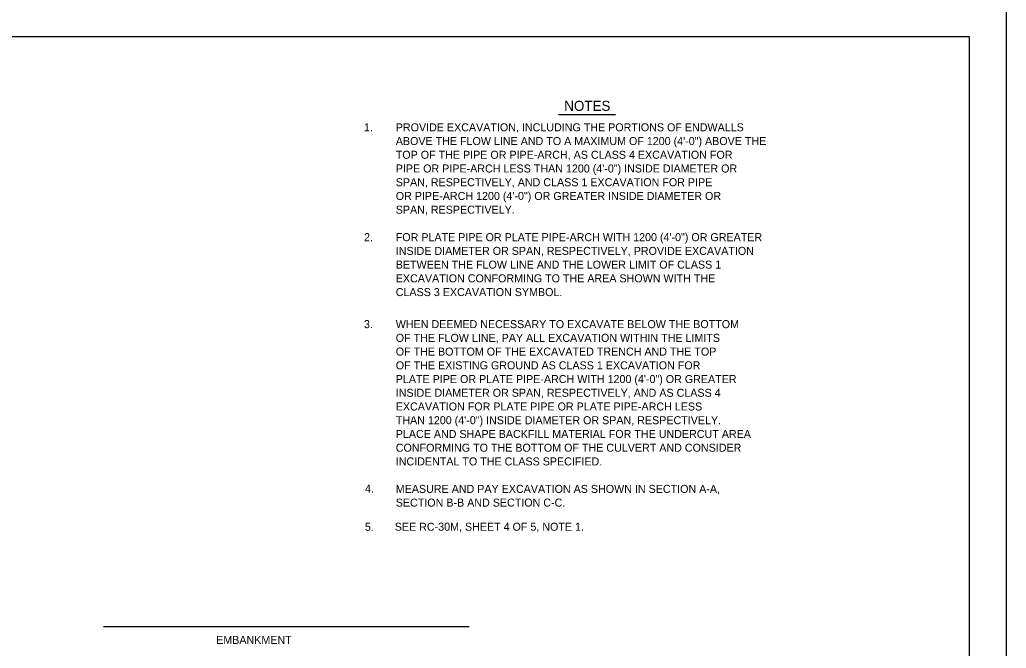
# Model space of a CAD drawing. Extents: x 638454 to 639358, y 297937 to 299125.
# Drawn here: x 638863.9 to 639295.1, y 298248.6 to 298523.2 of the extents above; entities that cross this region are included whole.
import ezdxf

# ---------------------------------------------------------------- set-up
doc = ezdxf.new("R2010")
doc.units = 0
for name, color, linetype in [('1', 7, 'Continuous'), ('2', 7, 'Continuous'), ('3', 7, 'Continuous'), ('4', 7, 'Continuous'), ('PLT-BNDY', 7, 'Continuous')]:
    doc.layers.add(name, color=color, linetype=linetype)

msp = doc.modelspace()

# ---------------------------------------------------------------- linework, layer by layer
at = {"layer": '1'}
msp.add_lwpolyline([(639279.11, 297951.7), (639279.11, 298515.7), (638493.11, 298515.7), (638493.11, 297951.7), (639279.11, 297951.7), (639279.11, 297978.05), (639079.11, 297978.05), (639079.11, 298042.73), (639279.11, 298042.73), (639279.11, 298071.7), (639079.11, 298071.7), (639079.11, 297951.7), (639157.91, 297951.7), (639157.91, 297978.05), (639157.91, 297951.7), (639234.91, 297951.7), (639234.91, 297978.05), (639234.91, 297965.74), (639279.11, 297965.74)], dxfattribs=at)
at = {"layer": '2'}
msp.add_line((639060.27, 298257.87), (638900.54, 298257.87), dxfattribs=at)
at = {"layer": '3'}
msp.add_line((639099.38, 298481.85), (639124.29, 298481.85), dxfattribs=at)
at = {"layer": 'PLT-BNDY'}
msp.add_lwpolyline([(638454.11, 298530.7), (639295.11, 298530.7), (639295.11, 297936.7), (638454.11, 297936.7)], close=True, dxfattribs=at)

# ---------------------------------------------------------------- texts
at = {"layer": '3'}
for s, height, p in [('NOTES', 4.375, (639101.9, 298483.39)), ('1.  ', 3.5, (639014.35, 298474.44)), ('PROVIDE EXCAVATION, INCLUDING THE PORTIONS OF ENDWALLS', 3.5, (639028.24, 298474.44)), ('ABOVE THE FLOW LINE AND TO A MAXIMUM OF 1200 (4\'-0") ABOVE THE', 3.5, (639028.24, 298468.44)), ('TOP OF THE PIPE OR PIPE-ARCH, AS CLASS 4 EXCAVATION FOR', 3.5, (639028.24, 298462.44)), ('PIPE OR PIPE-ARCH LESS THAN 1200 (4\'-0") INSIDE DIAMETER OR', 3.5, (639028.24, 298456.45)), ('SPAN, RESPECTIVELY, AND CLASS 1 EXCAVATION FOR PIPE', 3.5, (639028.24, 298450.44)), ('OR PIPE-ARCH 1200 (4\'-0") OR GREATER INSIDE DIAMETER OR', 3.5, (639028.24, 298444.44)), ('SPAN, RESPECTIVELY.', 3.5, (639028.24, 298438.45)), ('2.  ', 3.5, (639014.35, 298426.44)), ('FOR PLATE PIPE OR PLATE PIPE-ARCH WITH 1200 (4\'-0") OR GREATER', 3.5, (639028.24, 298426.44)), ('INSIDE DIAMETER OR SPAN, RESPECTIVELY, PROVIDE EXCAVATION', 3.5, (639028.24, 298420.44)), ('BETWEEN THE FLOW LINE AND THE LOWER LIMIT OF CLASS 1', 3.5, (639028.24, 298414.44)), ('EXCAVATION CONFORMING TO THE AREA SHOWN WITH THE', 3.5, (639028.24, 298408.45)), ('EX', 3.5, (639028.24, 298408.44)), ('CLASS 3 EXCAVATION SYMBOL.', 3.5, (639028.24, 298402.44)), ('3.  ', 3.5, (639014.35, 298388.44)), ('WHEN DEEMED NECESSARY TO EXCAVATE BELOW THE BOTTOM', 3.5, (639028.24, 298388.44)), ('OF THE FLOW LINE, PAY ALL EXCAVATION WITHIN THE LIMITS', 3.5, (639028.24, 298382.44)), ('OF THE BOTTOM OF THE EXCAVATED TRENCH AND THE TOP', 3.5, (639028.24, 298376.44)), ('OF THE EXISTING GROUND AS CLASS 1 EXCAVATION FOR ', 3.5, (639028.24, 298370.44)), ('OF', 3.5, (639028.24, 298370.44)), ('PLATE PIPE OR PLATE PIPE-ARCH WITH 1200 (4\'-0") OR GREATER', 3.5, (639028.24, 298364.44)), ('INSIDE DIAMETER OR SPAN, RESPECTIVELY, AND AS CLASS 4', 3.5, (639028.24, 298358.44)), ('EXCAVATION FOR PLATE PIPE OR PLATE PIPE-ARCH LESS', 3.5, (639028.24, 298352.45)), ('THAN 1200 (4\'-0") INSIDE DIAMETER OR SPAN, RESPECTIVELY.', 3.5, (639028.24, 298346.45)), ('PLACE AND SHAPE BACKFILL MATERIAL FOR THE UNDERCUT AREA', 3.5, (639028.24, 298340.44)), ('CONFORMING TO THE BOTTOM OF THE CULVERT AND CONSIDER', 3.5, (639028.24, 298334.44)), ('INCIDENTAL TO THE CLASS SPECIFIED.', 3.5, (639028.24, 298328.45)), ('4.  ', 3.5, (639014.78, 298316.57)), ('MEASURE AND PAY EXCAVATION AS SHOWN IN SECTION A-A,', 3.5, (639028.24, 298316.44)), ('SECTION B-B AND SECTION C-C.', 3.5, (639028.24, 298310.45)), ('5.', 3.5, (639014.73, 298299.88)), ('EMBANKMENT', 3.5, (638949.73, 298250.46))]:
    msp.add_text(s, height=height, dxfattribs=at).set_placement(p)
at = {"layer": '4'}
msp.add_text('SEE RC-30M, SHEET 4 OF 5, NOTE 1.', height=3.5, dxfattribs=at).set_placement((639027.8, 298299.91))

doc.saveas('drawing.dxf')
